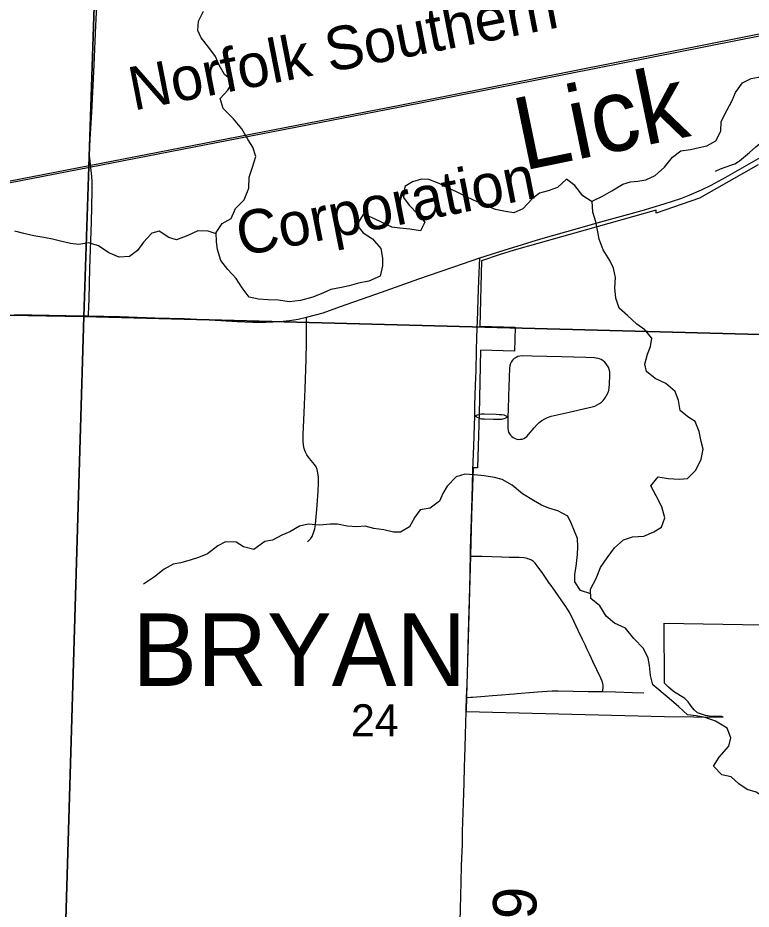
# Model space of a CAD drawing. Extents: x 0 to 34, y 0 to 22.
# Drawn here: x 4.658 to 5.615, y 16.807 to 17.97 of the extents above; entities that cross this region are included whole.
import ezdxf

# ---------------------------------------------------------------- set-up
doc = ezdxf.new("R2010")
doc.units = 0
for name, color, linetype in [('GM_X_City_Street', 7, 'Continuous'), ('GM_X_Corporation', 7, 'Continuous'), ('GM_X_Corporation_Text', 7, 'Continuous'), ('GM_X_County_Road', 7, 'Continuous'), ('GM_X_County_Road_Text', 7, 'Continuous'), ('GM_X_Minor_River', 7, 'Continuous'), ('GM_X_Minor_River_Text', 7, 'Continuous'), ('GM_X_Rail_Line', 7, 'Continuous'), ('GM_X_Rail_Line_Text', 7, 'Continuous'), ('GM_X_Section_Text', 7, 'Continuous'), ('GM_X_Township_Road', 7, 'Continuous')]:
    doc.layers.add(name, color=color, linetype=linetype)

msp = doc.modelspace()

# ---------------------------------------------------------------- linework, layer by layer
at = {"layer": 'GM_X_City_Street'}
for points in [[(5.2977, 17.4498), (5.2975, 17.4347), (5.298, 17.4318), (5.2987, 17.4296), (5.2998, 17.4275), (5.3011, 17.4257), (5.3028, 17.424), (5.3047, 17.4226), (5.3073, 17.4213), (5.3096, 17.4206), (5.3118, 17.4203), (5.3142, 17.4204), (5.3165, 17.4208), (5.3187, 17.4216), (5.3207, 17.4227), (5.3225, 17.4242), (5.3249, 17.4269), (5.3319, 17.4356), (5.3354, 17.4394), (5.3387, 17.4423), (5.3422, 17.445), (5.3461, 17.4472), (5.3495, 17.4489), (5.3543, 17.4505), (5.3622, 17.4525), (5.378, 17.456), (5.4023, 17.4614), (5.4077, 17.4626), (5.4112, 17.4638), (5.4145, 17.4652), (5.4175, 17.4671), (5.4199, 17.469), (5.422, 17.4711), (5.4247, 17.4744), (5.4267, 17.4774), (5.4283, 17.4807), (5.4294, 17.4841), (5.4301, 17.4876), (5.4305, 17.4925), (5.4308, 17.5043), (5.4307, 17.5085), (5.4301, 17.5115), (5.4294, 17.5137), (5.428, 17.5163), (5.4263, 17.5187), (5.4243, 17.5209), (5.422, 17.5228), (5.4195, 17.5244), (5.4173, 17.5254), (5.4151, 17.526), (5.4109, 17.5266), (5.3997, 17.5271), (5.368, 17.528), (5.3289, 17.5291), (5.3165, 17.5293), (5.3135, 17.529), (5.3107, 17.5283), (5.3085, 17.5273), (5.3061, 17.5257), (5.3044, 17.5241), (5.3026, 17.5218), (5.3012, 17.5192), (5.3002, 17.5164), (5.2997, 17.5134), (5.2993, 17.5011), (5.2985, 17.4769), (5.298, 17.4594), (5.2977, 17.4498)], [(5.2544, 17.4511), (5.2554, 17.4514), (5.2582, 17.4524), (5.2614, 17.4534), (5.2634, 17.4536), (5.2654, 17.4538), (5.267, 17.4538), (5.2824, 17.4533), (5.2863, 17.453), (5.2897, 17.4526), (5.2923, 17.4522), (5.2942, 17.4515), (5.2962, 17.4507), (5.2977, 17.4498)], [(5.2544, 17.4511), (5.2587, 17.4487), (5.2615, 17.4477), (5.2631, 17.4473), (5.2652, 17.4473), (5.267, 17.4472), (5.279, 17.4468), (5.2819, 17.4467), (5.2848, 17.4466), (5.2873, 17.4467), (5.2897, 17.4469), (5.2916, 17.4472), (5.2927, 17.4475), (5.2942, 17.4481), (5.2958, 17.4488), (5.2977, 17.4498)], [(5.4216, 17.0912), (5.4219, 17.0936), (5.4221, 17.0957), (5.4222, 17.0974), (5.4223, 17.0993), (5.4218, 17.1016), (5.4215, 17.1026), (5.4212, 17.1037), (5.4208, 17.1047), (5.4204, 17.1058), (5.4192, 17.1086), (5.4088, 17.1304), (5.407, 17.1343), (5.4043, 17.1399), (5.4009, 17.147), (5.399, 17.1513), (5.3952, 17.1591), (5.3897, 17.1709), (5.3812, 17.1888), (5.3776, 17.1954), (5.3734, 17.2022), (5.3692, 17.2084), (5.3624, 17.2179), (5.3543, 17.2295), (5.3524, 17.232), (5.351, 17.234), (5.3496, 17.236), (5.3433, 17.2453), (5.3361, 17.2554), (5.3334, 17.2588), (5.3311, 17.2609), (5.3297, 17.2619), (5.3285, 17.2626), (5.3257, 17.2639), (5.324, 17.2645), (5.3228, 17.2649), (5.3211, 17.2653), (5.3191, 17.2656), (5.3123, 17.2661), (5.2993, 17.2663), (5.29, 17.2666), (5.2639, 17.2673), (5.2546, 17.2675), (5.2488, 17.2677)], [(5.2439, 17.0837), (5.2493, 17.084), (5.2517, 17.0841), (5.2677, 17.0854), (5.2776, 17.0862), (5.29, 17.0871), (5.2999, 17.0879), (5.3061, 17.0884), (5.3098, 17.0887), (5.3314, 17.0905), (5.3425, 17.0914), (5.3555, 17.092), (5.3636, 17.0922), (5.4027, 17.0915), (5.4201, 17.0912), (5.4216, 17.0912), (5.4385, 17.0907), (5.4604, 17.0901), (5.4753, 17.0894)]]:
    msp.add_lwpolyline(points, dxfattribs=at)
at = {"layer": 'GM_X_Corporation'}
for points in [[(3.7435, 18.6067), (4.7775, 18.5857), (4.7439, 17.5807), (3.7219, 17.5988)], [(4.7775, 18.5857), (5.7749, 18.5522), (5.7585, 17.5867), (5.7581, 17.5537), (4.7439, 17.5807)], [(3.7219, 17.5988), (4.7439, 17.5807), (4.7141, 16.575), (3.7247, 16.5938)], [(4.7439, 17.5807), (5.7581, 17.5537), (5.7459, 16.557), (4.7141, 16.575)]]:
    msp.add_lwpolyline(points, close=True, dxfattribs=at)
msp.add_lwpolyline([(5.6247, 17.7788), (5.548, 17.7349), (5.4916, 17.7156), (5.4916, 17.7196), (5.3058, 17.6673), (5.2863, 17.6612), (5.2632, 17.6532), (5.2612, 17.568), (5.3074, 17.5666), (5.3065, 17.5353), (5.2622, 17.5366), (5.2602, 17.4538), (5.258, 17.3831), (5.2523, 17.3833), (5.2502, 17.3208), (5.2488, 17.2684), (5.2438, 17.0849), (5.2433, 17.0654), (5.5021, 17.0587), (5.5791, 17.0577), (5.577, 17.0585), (5.5631, 17.0589), (5.5559, 17.06), (5.5454, 17.0637), (5.5412, 17.0675), (5.5371, 17.0724), (5.5333, 17.078), (5.5288, 17.0821), (5.5141, 17.0912), (5.5077, 17.0968), (5.5025, 17.1022), (5.5019, 17.1803), (5.7575, 17.1762)], dxfattribs=at)
at = {"layer": 'GM_X_County_Road'}
for points in [[(4.7501, 17.5815), (4.7502, 17.5833), (4.7508, 17.6033), (4.752, 17.6436), (4.754, 17.7038), (4.7551, 17.7448), (4.7551, 17.756), (4.7545, 17.7636), (4.7533, 17.7747), (4.7527, 17.7793), (4.752, 17.7872), (4.7514, 17.7918), (4.7525, 17.8123), (4.7544, 17.847), (4.7573, 17.909), (4.7597, 17.9604), (4.7614, 17.9952), (4.7647, 18.0914), (4.7676, 18.1989), (4.7683, 18.2384)], [(5.5688, 17.7704), (5.5756, 17.7733), (5.5902, 17.7784), (5.5942, 17.7801), (5.5975, 17.7819), (5.6001, 17.7838), (5.6054, 17.788), (5.6132, 17.7946), (5.6215, 17.8019), (5.6266, 17.8063), (5.629, 17.8083)], [(5.261, 17.6574), (5.2927, 17.6674), (5.3409, 17.682), (5.3917, 17.6964), (5.4144, 17.703), (5.4731, 17.7191), (5.5017, 17.7275), (5.5235, 17.7348), (5.5345, 17.739), (5.5504, 17.7459), (5.5632, 17.7522), (5.5823, 17.7626), (5.6341, 17.7921), (5.6354, 17.7927)], [(5.035, 17.5796), (5.0566, 17.5856), (5.0794, 17.5936), (5.1327, 17.6125), (5.1813, 17.6299), (5.2095, 17.6396), (5.2272, 17.6455), (5.261, 17.6574)], [(5.2578, 17.5674), (5.2581, 17.5739), (5.259, 17.6037), (5.26, 17.6276), (5.261, 17.6574)], [(4.654, 17.5834), (4.7211, 17.5821), (4.7501, 17.5815)], [(4.7501, 17.5815), (4.7907, 17.5807), (4.8373, 17.5791), (4.8752, 17.578), (4.9087, 17.5762), (4.9441, 17.5741), (4.9646, 17.5733), (4.9819, 17.5734), (4.9999, 17.5743), (5.0128, 17.5755), (5.0238, 17.5772), (5.035, 17.5796)], [(5.2568, 17.5361), (5.2568, 17.5379), (5.2574, 17.551), (5.2578, 17.5674)], [(5.2544, 17.4511), (5.2544, 17.4526), (5.2547, 17.4646), (5.2556, 17.4912), (5.2562, 17.5104), (5.2568, 17.5361)], [(5.2488, 17.2677), (5.2491, 17.2773), (5.2498, 17.3031), (5.2505, 17.33), (5.251, 17.3451), (5.2515, 17.3607), (5.2522, 17.3806), (5.2532, 17.4116), (5.254, 17.4383), (5.2544, 17.4511)], [(5.2439, 17.0837), (5.2444, 17.1003), (5.2454, 17.1301), (5.2461, 17.1519), (5.2467, 17.183), (5.2475, 17.2115), (5.2483, 17.2439), (5.2484, 17.2514), (5.2488, 17.2677)], [(5.2434, 17.0647), (5.2434, 17.0686), (5.2439, 17.0837)], [(5.232, 16.5662), (5.2321, 16.5737), (5.2321, 16.587), (5.2321, 16.5976), (5.2323, 16.6106), (5.2325, 16.6269), (5.2328, 16.6542), (5.2333, 16.6964), (5.2343, 16.7368), (5.2347, 16.7616), (5.235, 16.7759), (5.2358, 16.8076), (5.2368, 16.8424), (5.2374, 16.8642), (5.2384, 16.8921), (5.2387, 16.9089), (5.2399, 16.9455), (5.2405, 16.9723), (5.2412, 16.9928), (5.2416, 17.0058), (5.242, 17.0181), (5.2425, 17.0353), (5.2434, 17.0647)]]:
    msp.add_lwpolyline(points, dxfattribs=at)
at = {"layer": 'GM_X_Minor_River'}
for points in [[(5.408, 17.7302), (5.3956, 17.7381), (5.3852, 17.7515), (5.3744, 17.7601), (5.3624, 17.749), (5.3502, 17.7446), (5.3392, 17.7418), (5.3295, 17.7344), (5.3175, 17.721), (5.3057, 17.7159), (5.2947, 17.7176), (5.2815, 17.7205), (5.2668, 17.7265), (5.2529, 17.7325), (5.2428, 17.7372), (5.2296, 17.7436), (5.2198, 17.7483), (5.2082, 17.7542), (5.1946, 17.7594), (5.1848, 17.76), (5.1733, 17.7564), (5.163, 17.7502), (5.1616, 17.7361), (5.169, 17.7261), (5.1797, 17.7145), (5.1894, 17.7037), (5.1835, 17.6925), (5.1699, 17.6946), (5.1566, 17.696), (5.1464, 17.6973), (5.1318, 17.7041), (5.1186, 17.7104), (5.1088, 17.7136), (5.1006, 17.7001), (5.1087, 17.6897), (5.1211, 17.6819), (5.1318, 17.6692), (5.1339, 17.6566), (5.1341, 17.6467), (5.1312, 17.6335), (5.1162, 17.627), (5.1029, 17.6242), (5.0903, 17.6206), (5.0804, 17.6185), (5.0664, 17.6158), (5.0568, 17.6114), (5.043, 17.606), (5.027, 17.6017), (5.0122, 17.5997), (4.9982, 17.6019), (4.9846, 17.6026), (4.9721, 17.6032), (4.96, 17.6061), (4.9507, 17.618), (4.943, 17.6303), (4.9322, 17.6419), (4.923, 17.6538), (4.9187, 17.668), (4.9174, 17.6782), (4.9169, 17.6904), (4.9247, 17.702), (4.9366, 17.7086), (4.9421, 17.7214), (4.9533, 17.733), (4.9593, 17.748), (4.96, 17.7624), (4.9644, 17.7756), (4.9685, 17.7896), (4.9645, 17.8018), (4.9586, 17.8114), (4.9502, 17.8256), (4.9394, 17.8387), (4.9261, 17.8523), (4.9221, 17.8653), (4.9322, 17.8761), (4.9392, 17.8873), (4.9277, 17.8963), (4.9207, 17.9086), (4.916, 17.92), (4.9071, 17.9316), (4.8971, 17.9443), (4.8931, 17.9539), (4.8937, 17.966), (4.9001, 17.9792)], [(5.5084, 17.082), (5.4872, 17.1002), (5.484, 17.1124), (5.4827, 17.1254), (5.481, 17.1349), (5.4748, 17.1475), (5.4622, 17.1603), (5.4514, 17.1742), (5.4372, 17.1805), (5.4263, 17.1898), (5.4179, 17.2033), (5.4063, 17.2126), (5.4058, 17.2248), (5.4129, 17.2387), (5.4188, 17.253), (5.4274, 17.2657), (5.4368, 17.2788), (5.4487, 17.2892), (5.4606, 17.2931), (5.4754, 17.294), (5.4884, 17.2998), (5.4984, 17.3057), (5.5028, 17.3178), (5.4989, 17.3323), (5.4912, 17.3468), (5.4846, 17.3599), (5.4939, 17.3714), (5.5072, 17.3693), (5.5219, 17.3682), (5.5322, 17.3692), (5.543, 17.38), (5.5501, 17.3943), (5.5526, 17.4075), (5.5502, 17.4174), (5.5474, 17.4307), (5.5423, 17.4437), (5.5326, 17.4496), (5.5229, 17.4582), (5.5205, 17.4711), (5.5162, 17.483), (5.5039, 17.4934), (5.4903, 17.4998), (5.4788, 17.5087), (5.4767, 17.5183), (5.48, 17.5315), (5.4839, 17.5417), (5.4857, 17.5522), (5.4764, 17.5631), (5.4663, 17.5708), (5.454, 17.5821), (5.4432, 17.5914), (5.4389, 17.6044), (5.4376, 17.6181), (5.4383, 17.6317), (5.4355, 17.6439), (5.4307, 17.6539), (5.4223, 17.6677), (5.4169, 17.6815), (5.4152, 17.691), (5.4124, 17.704), (5.4085, 17.7169), (5.408, 17.731), (5.4214, 17.7379), (5.4336, 17.7445), (5.4478, 17.7534), (5.4578, 17.7566), (5.4676, 17.7572), (5.4779, 17.7589), (5.4901, 17.7647), (5.5021, 17.7755), (5.5126, 17.7885), (5.5234, 17.7967), (5.5363, 17.7987), (5.5477, 17.8011), (5.5576, 17.8032), (5.5691, 17.8098), (5.5758, 17.8226), (5.5761, 17.8351), (5.5835, 17.8494), (5.5906, 17.8626), (5.595, 17.8731), (5.6043, 17.8854), (5.6154, 17.8913), (5.6299, 17.8937)], [(4.9169, 17.6886), (4.9063, 17.6921), (4.893, 17.6924), (4.88, 17.6862), (4.8651, 17.6808), (4.8549, 17.6836), (4.8426, 17.6922), (4.833, 17.6894), (4.8218, 17.6778), (4.814, 17.667), (4.8036, 17.6588), (4.79, 17.6583), (4.7768, 17.6639), (4.763, 17.6729), (4.7505, 17.6769), (4.7376, 17.6745), (4.7266, 17.6759), (4.7134, 17.6791), (4.7032, 17.6816), (4.6919, 17.6837), (4.6786, 17.6859), (4.6658, 17.6888), (4.6537, 17.6921)], [(5.406, 17.2187), (5.3925, 17.2231), (5.3851, 17.2346), (5.3853, 17.2445), (5.387, 17.2543), (5.3885, 17.2703), (5.389, 17.2801), (5.3885, 17.2911), (5.3849, 17.3007), (5.3809, 17.3103), (5.3761, 17.3202), (5.363, 17.3273), (5.3513, 17.3306), (5.3415, 17.3345), (5.3314, 17.3404), (5.3168, 17.3494), (5.3034, 17.3607), (5.2902, 17.3678), (5.2804, 17.3706), (5.2668, 17.3728), (5.2536, 17.3742), (5.2414, 17.3748), (5.2304, 17.3716), (5.2184, 17.3593), (5.2129, 17.3496), (5.2085, 17.3398), (5.1962, 17.3305), (5.1833, 17.3285), (5.1763, 17.3188), (5.1692, 17.3064), (5.1577, 17.2994), (5.1482, 17.2992), (5.1358, 17.3025), (5.1225, 17.3039), (5.1116, 17.3071), (5.1006, 17.3062), (5.0881, 17.3072), (5.0752, 17.3097), (5.0658, 17.3095), (5.0521, 17.3083), (5.0369, 17.3097), (5.0255, 17.3069), (5.0132, 17.2995), (5.0025, 17.2952), (4.9906, 17.2886), (4.9804, 17.2869), (4.9658, 17.2765), (4.9526, 17.2802), (4.9428, 17.2861), (4.9292, 17.2867), (4.9188, 17.2816), (4.9057, 17.2709), (4.8939, 17.2662), (4.884, 17.2633), (4.8706, 17.2594), (4.8607, 17.2573), (4.8489, 17.2511), (4.8362, 17.2411), (4.8219, 17.2315)], [(5.6964, 16.8992), (5.6867, 16.9055), (5.677, 16.9136), (5.6674, 16.9267), (5.6561, 16.9342), (5.6434, 16.9416), (5.6356, 16.9512), (5.6221, 16.9599), (5.6104, 16.9635), (5.5992, 16.9709), (5.5895, 16.9798), (5.5771, 16.9824), (5.5663, 16.994), (5.5737, 17.0056), (5.5865, 17.0201), (5.589, 17.0307), (5.5839, 17.0437), (5.5689, 17.0527), (5.5554, 17.0575), (5.5437, 17.0597), (5.5323, 17.061), (5.5211, 17.0715), (5.5084, 17.082)]]:
    msp.add_lwpolyline(points, dxfattribs=at)
at = {"layer": 'GM_X_Rail_Line'}
for points in [[(2.1, 17.2578), (2.1839, 17.2743), (2.7373, 17.3807), (3.3215, 17.4979), (3.9612, 17.6228), (4.5554, 17.74), (5.1565, 17.8564), (5.7754, 17.979), (6.3342, 18.0908), (6.9022, 18.2018), (7.3492, 18.2882), (7.4239, 18.3027), (8.0092, 18.4168), (8.4623, 18.5082), (8.9, 18.5958)], [(2.1, 17.2555), (2.1844, 17.272), (2.7377, 17.3784), (3.3219, 17.4956), (3.9616, 17.6205), (4.5558, 17.7377), (5.157, 17.8541), (5.7759, 17.9767), (6.3346, 18.0885), (6.9026, 18.1995), (7.3496, 18.2859), (7.4243, 18.3004), (8.0097, 18.4146), (8.4624, 18.5056), (8.9, 18.5934)]]:
    msp.add_lwpolyline(points, dxfattribs=at)
at = {"layer": 'GM_X_Township_Road'}
msp.add_lwpolyline([(5.0361, 17.2866), (5.0399, 17.2907), (5.042, 17.2937), (5.0432, 17.2961), (5.044, 17.2983), (5.0449, 17.301), (5.0455, 17.3036), (5.046, 17.3064), (5.0464, 17.3098), (5.0482, 17.329), (5.0499, 17.3525), (5.0505, 17.3637), (5.0504, 17.3711), (5.0498, 17.3767), (5.0488, 17.3809), (5.0474, 17.3843), (5.0454, 17.3875), (5.0386, 17.3956), (5.0354, 17.4001), (5.0331, 17.4045), (5.0316, 17.4086), (5.0308, 17.4129), (5.0305, 17.4184), (5.0306, 17.4265), (5.0316, 17.4551), (5.033, 17.4861), (5.0344, 17.5246), (5.035, 17.5469), (5.0348, 17.5655), (5.035, 17.5796)], dxfattribs=at)

# ---------------------------------------------------------------- texts
at = {"layer": 'GM_X_Corporation_Text'}
msp.add_text('BRYAN', height=0.0947, rotation=0, dxfattribs=at).set_placement((4.8073, 17.0986))
at = {"layer": 'GM_X_County_Road_Text'}
msp.add_text('C-179', height=0.05682, rotation=88.9096, dxfattribs=at).set_placement((5.3316, 16.629))
at = {"layer": 'GM_X_Minor_River_Text'}
msp.add_text('Lick', height=0.09476, rotation=11.671, dxfattribs=at).set_placement((5.3175, 17.7708))
at = {"layer": 'GM_X_Rail_Line_Text'}
for s, rotation, p in [('Norfolk Southern', 11.0655, (4.8088, 17.8492)), ('Corporation', 11.1636, (4.9493, 17.6592))]:
    msp.add_text(s, height=0.056629, rotation=rotation, dxfattribs=at).set_placement(p)
at = {"layer": 'GM_X_Section_Text'}
msp.add_text('24', height=0.04186, rotation=0, dxfattribs=at).set_placement((5.0929, 17.0328))

doc.saveas('drawing.dxf')
